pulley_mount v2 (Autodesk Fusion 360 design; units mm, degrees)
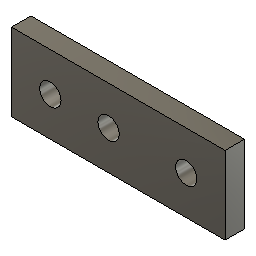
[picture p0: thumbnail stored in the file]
sketch "Sketch1" plane through (0, 0, 0) normal (0, 0, 1) x axis (1, 0, 0)
  line L1 (65, 15) -> (10, 15)
  line L2 (65, 35) -> (65, 15)
  line L3 (10, 35) -> (65, 35)
  line L4 (10, 15) -> (10, 35)
  line L5 (65, 35) -> (10, 15)
  line L6 (10, 35) -> (65, 15)
  line L7 (20, 5) -> (20, 45)
  line L8 (35, 45) -> (35, 5)
  line L9 (55, 5) -> (55, 45)
  line L10 (72.658, 25) -> (2.8161, 25)
  circle C1 centre (20, 25) radius 2.75
  circle C2 centre (35, 25) radius 2.75
  circle C3 centre (55, 25) radius 2.75
  point P6 (37.5, 25)
  point P15 (20, 25)
  point P16 (35, 25)
  point P17 (55, 25)
  point P2 (10, 15)
  point P5 (10, 35)
  point P4 (65, 35)
  horizontal L1
  perpendicular L1 L2
  parallel L1 L3
  parallel L2 L4
  coincident L5 P6
  coincident L6 P6
  perpendicular L1 L7
  perpendicular L3 L8
  parallel L8 L9
  perpendicular L2 L10
  midpoint L7 P15
  midpoint L8 P16
  midpoint L9 P17
  dimension "d1" distance P2 P5 = 20
  dimension "d2" distance P4 P5 = 55
  dimension "d3" distance L4 L7 = 10
  dimension "d4" distance L4 L8 = 25
  dimension "d5" distance L4 L9 = 45
  dimension "d6" diameter C1 = 5.5
  dimension "d7" diameter C2 = 5.5
  dimension "d8" diameter C3 = 5.5
extrude "Extrude1" new body sketch "Sketch1" profile of L1 L2 L3 L4 C1 C2 C3 along normal blind 6
sketch "Sketch3" plane through (0, 0, 6) normal (0, 0, 1) x axis (1, 0, 0)
  line L1 (10, 15) -> (10, 35)
  line L2 (65, 15) -> (10, 15)
  line L3 (65, 35) -> (65, 15)
  line L4 (10, 35) -> (65, 35)
  line L5 (10, 35) -> (65, 35)
  line L6 (65, 35) -> (65, 15)
  line L7 (65, 15) -> (10, 15)
  line L8 (10, 15) -> (10, 35)
  circle C1 centre (20, 25) radius 2.75
  circle C2 centre (55, 25) radius 2.75
  circle C3 centre (35, 25) radius 2.75
  circle C4 centre (35, 25) radius 2.75
  circle C5 centre (55, 25) radius 2.75
  circle C6 centre (20, 25) radius 2.75
extrude "Extrude2" new body sketch "Sketch3" along normal blind 5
